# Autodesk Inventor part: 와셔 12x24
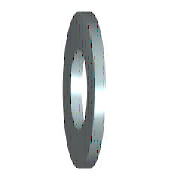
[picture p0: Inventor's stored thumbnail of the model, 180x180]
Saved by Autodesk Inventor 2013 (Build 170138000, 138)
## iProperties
IsCustomPart: 1
Created: 2012-02
Part Number: 와셔 12x24
Material: 스테인리스강
Description: 평면 와셔
Document SubType Name: Modeling
Standard: KS B 1326
Designer: mduedu
Standards Organization: KS
Language: ko-KR
Size Designation: 12x24
Categories: <MemberInstance><Categories><Category DisplayName="조임쇠" InternalName="e4da775c-781d-43d5-af7c-5136215cf5a6" Mnemonic="FSTN"><Category DisplayName="와셔" InternalN
Density: 1 g/cm^3
Author: mduedu
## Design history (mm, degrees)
sketch "스케치"
  geometry: C1 r 12 at (0, 0); C2 r 6.5 at (0, 0); 1 further point
  constraints: 2 centre point, 2 coincident
  dimensions: "d0" = 13 diameter of C2 (= SD1); "d1" = 24 diameter of C1 (= SD2)
extrude "본체" new body sketch "스케치" distance "d2" = 3 (= SD); taper "d3" = 0 deg
workaxis "Work Axis1"
workplane "Work Plane1"
body "Solid1"
other parameters: "SD1" = 13 [user parameter; used in 1 equation term], "SD2" = 24 [user parameter; used in 1 equation term], "SD" = 3 [user parameter; used in 1 equation term], "d4" = 0, "d5" = 0, "d6" = 0, "d7" = 0, "NND" = 12 [user parameter]
